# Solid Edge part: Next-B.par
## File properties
Title: Next/B
Author: Desys
Template: Normal.par
Last saved by: Luca
Revision: 3
Application: Solid Edge
Tipo di contenuto documento: 0
Precisione: 0.990
Document Number: 8047/B
Revision: 0
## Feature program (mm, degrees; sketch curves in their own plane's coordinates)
body "unnamed Body 1"
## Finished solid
Body 1: solid body, 158 faces, 347 edges, 191 vertices.
  Faces by surface: cylinder 61, torus 36, plane 24, spline 23, cone 8, sphere 6
  Edges by curve: circle 142, line 117, curve on surface 88
Bounding box of the edges (mm; curved faces can reach further): 410.000 x 500.000 x 135.000, from (-205, -250, 0) to (205, 250, 135).
Cylindrical faces by radius (mm): R2 x18, R5 x23, R10 x7, R17.5 x1, R25 x1, R40 x4, R56 x4, R130 x2, R272.5 x1
Conical faces (half-angle, radius in mm at the cone's reference point): 8 deg R78.6771 x4, 8 deg R103.916 x2, 10 deg R44.75 x1, 45 deg R26.4645 x1
Toroidal faces (ring radius, tube radius in mm): R3 r2 x2, R12 r2 x4, R19.5 r2 x2, R30 r5 x1, R39.0663 r40 x4, R39.0663 r56 x4, R42.0711 r5 x1, R46.6782 r2 x1, R70 r10 x2, R84.6321 r5 x2, R94.3464 r5 x4, R98.9086 r5 x2, R108.8171 r5 x2, R125 r5 x2, R128 r2 x2, R274.5 r2 x1
Spherical faces by radius (mm): R2 x4, R5 x2
Planar faces by outward normal: +x 2, +y 1, +z 4, -x 2, -y 1, -z 6, oblique 8
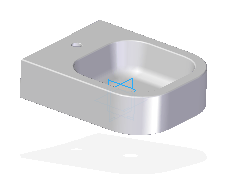
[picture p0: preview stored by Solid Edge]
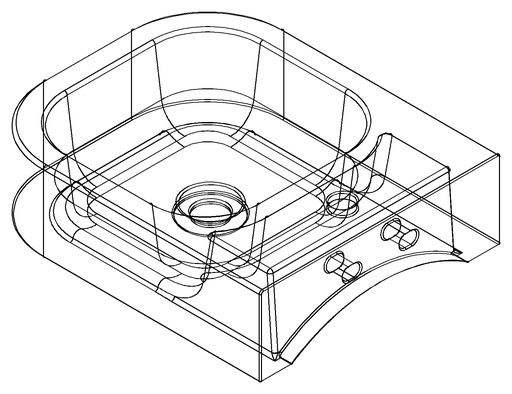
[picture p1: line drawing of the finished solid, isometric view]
